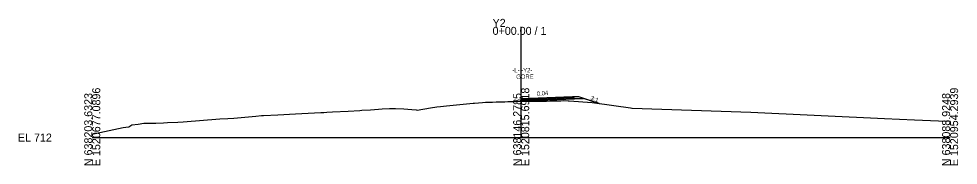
# Model space of a CAD drawing. Extents: x -26 to 1603, y -10 to 1019.
# Drawn here: x -25.7 to 302.8, y -9.7 to 41.6 of the extents above; entities that cross this region are included whole.
import ezdxf

# ---------------------------------------------------------------- set-up
doc = ezdxf.new("R2010")
doc.units = 0
for name, color, linetype in [('Exist Cross Section Cell', 7, 'Continuous'), ('Exist XS Center Line Elevation Label', 7, 'Continuous'), ('Exist XS Ground Line', 7, 'Continuous'), ('Prop CMT Pvmt Course 1', 7, 'Continuous'), ('Prop CMT Pvmt Course 2', 7, 'Continuous'), ('Prop CMT Pvmt Course 3', 7, 'Continuous'), ('Prop CMT Pvmt Surface', 7, 'Continuous'), ('Prop CMT Slope Grass', 7, 'Continuous'), ('Prop CMT Subgrade Earthwork', 7, 'Continuous'), ('Prop XS Earthwork Shape', 7, 'Continuous'), ('Prop XS Shear Point Label', 7, 'Continuous')]:
    doc.layers.add(name, color=color, linetype=linetype)

msp = doc.modelspace()

# ---------------------------------------------------------------- linework, layer by layer
at = {"layer": 'Exist Cross Section Cell'}
for p, q in [((150, 0), (150, 38.78)), ((0, 0), (150, 0)), ((150, 0), (300, 0))]:
    msp.add_line(p, q, dxfattribs=at)
at = {"layer": 'Exist XS Ground Line'}
msp.add_lwpolyline([(0, 1.14), (1, 1.37), (10.81, 3.53), (11.72, 3.6), (12.75, 3.77), (13.86, 4.47), (16, 4.66), (18.03, 5), (20.49, 5.06), (22.2, 5.1), (24.91, 5.18), (26.3, 5.3), (29.96, 5.42), (31.82, 5.48), (44.64, 6.53), (47.36, 6.7), (49.57, 6.85), (57.15, 7.5), (59.24, 7.68), (59.92, 7.72), (64.85, 7.93), (71.13, 8.31), (79.95, 8.76), (81.04, 8.82), (82, 8.87), (83.99, 9), (89.53, 9.29), (93.62, 9.54), (94.25, 9.56), (97.36, 9.74), (100.07, 9.98), (101.35, 10.04), (103.95, 10.14), (104.88, 10.17), (106, 10.15), (109, 10.03), (111.72, 9.82), (113.31, 9.67), (113.67, 9.62), (118.27, 10.45), (120.51, 10.8), (121.73, 10.88), (123.87, 11.11), (133.18, 12.03), (133.67, 12.07), (136.43, 12.33), (137.51, 12.39), (137.97, 12.42), (139.05, 12.43), (139.97, 12.45), (141.23, 12.48), (142.68, 12.52), (144.27, 12.56), (145.38, 12.58), (146.16, 12.6), (148.07, 12.65), (150.09, 12.71), (150.8, 12.71), (153.47, 12.76), (155.36, 12.78), (156.16, 12.78), (156.49, 12.79), (157.31, 12.79), (158.43, 12.8), (158.88, 12.81), (159.99, 12.83), (161.58, 12.85), (162.24, 12.86), (163.83, 12.9), (164.65, 12.93), (166.44, 12.92), (166.77, 12.89), (174.87, 12.25), (180, 11.54), (182.41, 11.22), (188.23, 10.37), (188.75, 10.29), (188.8, 10.29), (230.34, 8.87), (277.05, 6.67), (287.54, 6.17), (295.99, 5.84), (300, 5.78)], dxfattribs=at)
at = {"layer": 'Prop CMT Pvmt Course 1'}
msp.add_line((150, 13.69), (168, 14.41), dxfattribs=at)
at = {"layer": 'Prop CMT Pvmt Course 2'}
for p, q in [((150, 13.44), (168.24, 14.17)), ((164, 14.25), (164, 13.42))]:
    msp.add_line(p, q, dxfattribs=at)
at = {"layer": 'Prop CMT Pvmt Course 3'}
msp.add_line((150, 13.11), (168.56, 13.85), dxfattribs=at)
at = {"layer": 'Prop CMT Pvmt Surface'}
msp.add_line((150, 13.69), (168, 14.41), dxfattribs=at)
at = {"layer": 'Prop CMT Slope Grass'}
for p, q in [((150, 13.69), (150, 12.7)), ((168, 14.41), (170, 14.34)), ((170, 14.34), (177.29, 11.91))]:
    msp.add_line(p, q, dxfattribs=at)
at = {"layer": 'Prop CMT Subgrade Earthwork'}
for p, q in [((150, 12.86), (171.82, 13.73)), ((150, 13.69), (150, 12.86)), ((150, 13.69), (150, 12.86)), ((168, 14.41), (168.8, 13.61))]:
    msp.add_line(p, q, dxfattribs=at)
at = {"layer": 'Prop XS Earthwork Shape'}
msp.add_lwpolyline([(150, 12.7), (150.09, 12.71), (150.8, 12.71), (153.47, 12.76), (155.36, 12.78), (156.16, 12.78), (156.49, 12.79), (157.31, 12.79), (158.43, 12.8), (158.88, 12.81), (159.99, 12.83), (161.58, 12.85), (162.24, 12.86), (163.83, 12.9), (164.65, 12.93), (166.44, 12.92), (166.77, 12.89), (174.87, 12.25), (177.29, 11.91), (171.82, 13.73), (168.8, 13.61), (150, 12.86)], close=True, dxfattribs=at)
at = {"layer": 'Prop XS Shear Point Label'}
msp.add_line((150, 0.42), (150, 20.02), dxfattribs=at)

# ---------------------------------------------------------------- texts
at = {"layer": 'Exist Cross Section Cell'}
for s, p in [('Y2', (140, 38.78)), ('0+00.00 / 1', (140, 35.98)), ('EL 712', (-26, -1.4))]:
    msp.add_text(s, height=2.8, dxfattribs=at).set_placement(p)
for s, p in [('E 1520677.0896', (2.8, -10)), ('E 1520815.6918', (152.8, -10)), ('E 1520954.2939', (302.8, -10)), ('N 638203.6323', (0, -10)), ('N 638146.2785', (150, -10)), ('N 638088.9248', (300, -10))]:
    msp.add_text(s, height=2.8, rotation=90, dxfattribs=at).set_placement(p)
at = {"layer": 'Exist XS Center Line Elevation Label'}
for s, p in [('-L- -Y2-', (146.91, 22.86)), ('GORE', (148.26, 20.61))]:
    msp.add_text(s, height=1.5, dxfattribs=at).set_placement(p)
for s, rotation, p in [('0.04', 5.0512, (155.5, 14.59)), ('3:1', 340.1643, (174.09, 13.3))]:
    msp.add_text(s, height=1.5, rotation=rotation, dxfattribs=at).set_placement(p)

doc.saveas('drawing.dxf')
